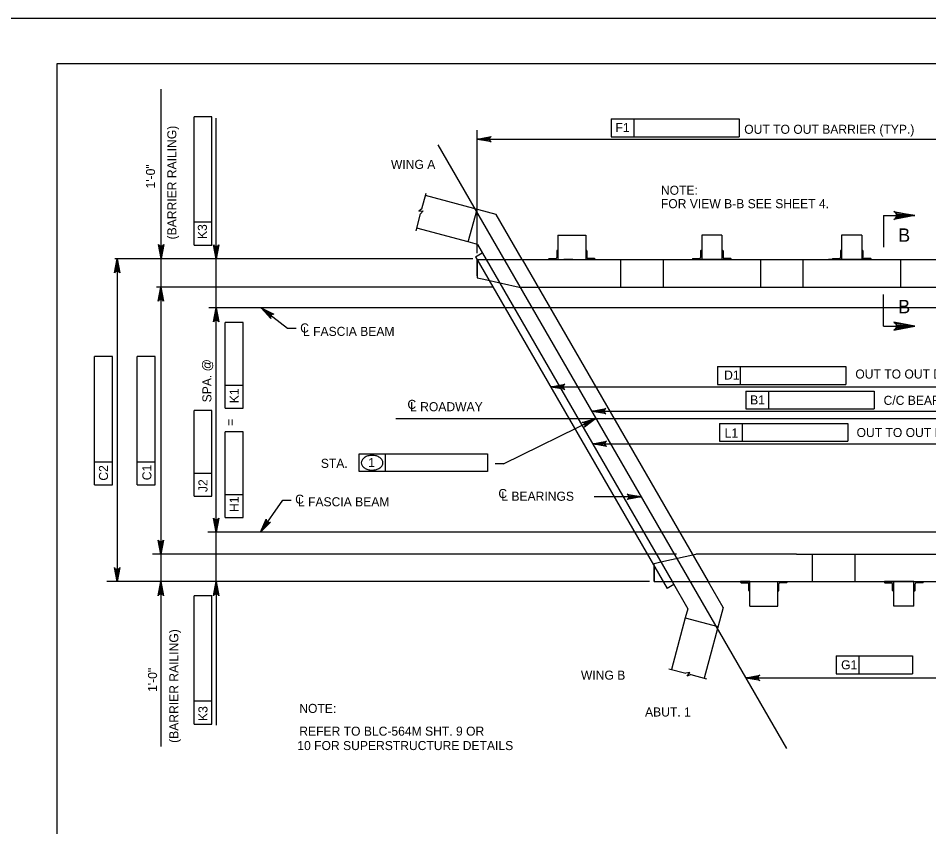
# Model space of a CAD drawing. Extents: x 638175 to 640495, y 294277 to 298435.
# Drawn here: x 639303.6 to 639605.4, y 298167.4 to 298435.5 of the extents above; entities that cross this region are included whole.
import ezdxf

# ---------------------------------------------------------------- set-up
doc = ezdxf.new("R2010")
doc.units = 0
for name, color, linetype in [('2', 7, 'Continuous'), ('3', 7, 'Continuous'), ('4', 7, 'Continuous'), ('PLT-BNDY', 7, 'Continuous')]:
    doc.layers.add(name, color=color, linetype=linetype)

msp = doc.modelspace()

# ---------------------------------------------------------------- linework, layer by layer
at = {"layer": '2'}
for p, q in [((639316.46, 297856.46), (639316.46, 298420.46)), ((639316.46, 298420.46), (640102.46, 298420.46)), ((639462.01, 298370.37), (639438.58, 298376.65)), ((639452.77, 298361.28), (639455.66, 298372.08)), ((639470.64, 298355.43), (639462.01, 298370.37)), ((639590.33, 298370.09), (639590.33, 298359.6)), ((639590.33, 298370.09), (639600.81, 298370.09)), ((639452.77, 298361.28), (639435.69, 298365.86)), ((639482.46, 298363.52), (639491.7, 298363.52)), ((639482.46, 298363.52), (639482.46, 298355.43)), ((639491.7, 298363.52), (639491.7, 298355.43)), ((639536.85, 298363.52), (639530.13, 298363.52)), ((639530.13, 298363.52), (639530.13, 298355.43)), ((639536.85, 298363.52), (639536.85, 298355.43)), ((639583.22, 298363.52), (639576.49, 298363.52)), ((639576.49, 298363.52), (639576.49, 298355.43)), ((639583.22, 298363.52), (639583.22, 298355.43)), ((639455.79, 298360.47), (639452.77, 298361.28)), ((639455.79, 298360.47), (639458.7, 298355.43)), ((639455.17, 298356.38), (639457.41, 298357.67)), ((639482.1, 298358.34), (639482.1, 298356.15)), ((639482.28, 298358.52), (639482.46, 298358.52)), ((639482.46, 298358.52), (639482.46, 298355.43)), ((639491.88, 298358.52), (639491.7, 298358.52)), ((639491.7, 298358.52), (639491.7, 298355.43)), ((639492.06, 298358.34), (639492.06, 298356.15)), ((639529.76, 298358.34), (639529.76, 298356.15)), ((639529.95, 298358.52), (639530.13, 298358.52)), ((639530.13, 298358.52), (639530.13, 298355.43)), ((639537.04, 298358.52), (639536.85, 298358.52)), ((639536.85, 298358.52), (639536.85, 298355.43)), ((639537.22, 298358.34), (639537.22, 298356.15)), ((639576.13, 298358.34), (639576.13, 298356.15)), ((639576.31, 298358.52), (639576.49, 298358.52)), ((639576.49, 298358.52), (639576.49, 298355.43)), ((639583.4, 298358.52), (639583.22, 298358.52)), ((639583.22, 298358.52), (639583.22, 298355.43)), ((639583.58, 298358.34), (639583.58, 298356.15)), ((639455.17, 298356.38), (639518.64, 298246.45)), ((639455.72, 298355.43), (639660.35, 298355.43)), ((639455.72, 298355.43), (639455.72, 298349.4)), ((639455.72, 298350.04), (639455.72, 298355.43)), ((639458.7, 298355.43), (639520.32, 298248.7)), ((639470.64, 298355.43), (639532.26, 298248.7)), ((639479.37, 298355.61), (639479.37, 298355.43)), ((639479.55, 298355.79), (639481.74, 298355.79)), ((639482.46, 298355.43), (639491.7, 298355.43)), ((639487.46, 298355.43), (639484.37, 298355.43)), ((639491.7, 298355.43), (639494.79, 298355.43)), ((639494.61, 298355.79), (639492.43, 298355.79)), ((639494.79, 298355.61), (639494.79, 298355.43)), ((639503.25, 298355.43), (639503.25, 298346.31)), ((639517.32, 298355.43), (639517.32, 298346.31)), ((639527.04, 298355.61), (639527.04, 298355.43)), ((639530.13, 298355.43), (639527.04, 298355.43)), ((639527.22, 298355.79), (639529.4, 298355.79)), ((639538.11, 298355.43), (639528.87, 298355.43)), ((639536.85, 298355.43), (639530.13, 298355.43)), ((639536.85, 298355.43), (639539.95, 298355.43)), ((639539.76, 298355.79), (639537.58, 298355.79)), ((639539.95, 298355.61), (639539.95, 298355.43)), ((639549.66, 298355.43), (639549.66, 298346.31)), ((639563.68, 298355.43), (639563.69, 298346.31)), ((639575.24, 298355.43), (639572.15, 298355.43)), ((639573.4, 298355.61), (639573.4, 298355.43)), ((639576.49, 298355.43), (639573.4, 298355.43)), ((639573.58, 298355.79), (639575.76, 298355.79)), ((639584.47, 298355.43), (639575.24, 298355.43)), ((639583.22, 298355.43), (639576.49, 298355.43)), ((639583.22, 298355.43), (639586.31, 298355.43)), ((639586.13, 298355.79), (639583.95, 298355.79)), ((639584.47, 298355.43), (639587.56, 298355.43)), ((639586.31, 298355.61), (639586.31, 298355.43)), ((639596.02, 298355.43), (639596.02, 298346.31)), ((639455.72, 298349.4), (639457.89, 298348.91)), ((639457.89, 298348.91), (639469.57, 298346.31)), ((639469.57, 298346.31), (639646.49, 298346.31)), ((639590.33, 298333.36), (639590.33, 298343.84)), ((639590.33, 298333.36), (639600.81, 298333.36)), ((639516.53, 298255.22), (639528.2, 298257.82)), ((639561.51, 298257.82), (639528.2, 298257.82)), ((639561.51, 298257.82), (639707.31, 298257.82)), ((639566.89, 298248.7), (639566.89, 298257.82)), ((639580.96, 298248.7), (639580.96, 298257.82)), ((639514.35, 298254.73), (639516.53, 298255.22)), ((639514.35, 298248.7), (639514.35, 298254.73)), ((639514.35, 298253.87), (639514.35, 298248.7)), ((639514.35, 298248.7), (639718.99, 298248.7)), ((639520.32, 298248.7), (639525.5, 298239.72)), ((639537.19, 298240.16), (639532.26, 298248.7)), ((639543.01, 298248.52), (639543.01, 298248.7)), ((639546.1, 298248.7), (639543.01, 298248.7)), ((639543.19, 298248.34), (639545.37, 298248.34)), ((639546.1, 298248.7), (639555.34, 298248.7)), ((639546.1, 298245.61), (639546.1, 298248.7)), ((639546.1, 298240.61), (639546.1, 298248.7)), ((639555.34, 298248.7), (639558.43, 298248.7)), ((639555.34, 298245.61), (639555.34, 298248.7)), ((639555.34, 298240.61), (639555.34, 298248.7)), ((639558.25, 298248.34), (639556.06, 298248.34)), ((639558.43, 298248.52), (639558.43, 298248.7)), ((639590.67, 298248.52), (639590.67, 298248.7)), ((639593.76, 298248.7), (639590.67, 298248.7)), ((639590.85, 298248.34), (639593.04, 298248.34)), ((639600.49, 298248.7), (639593.76, 298248.7)), ((639593.76, 298245.61), (639593.76, 298248.7)), ((639593.76, 298240.61), (639593.76, 298248.7)), ((639600.49, 298245.61), (639600.49, 298248.7)), ((639600.49, 298248.7), (639603.58, 298248.7)), ((639600.49, 298240.61), (639600.49, 298248.7)), ((639603.4, 298248.34), (639601.22, 298248.34)), ((639603.58, 298248.52), (639603.58, 298248.7)), ((639520.87, 298247.75), (639518.64, 298246.45)), ((639545.74, 298245.79), (639545.74, 298247.97)), ((639545.92, 298245.61), (639546.1, 298245.61)), ((639555.52, 298245.61), (639555.34, 298245.61)), ((639555.7, 298245.79), (639555.7, 298247.97)), ((639593.4, 298245.79), (639593.4, 298247.97)), ((639593.58, 298245.61), (639593.76, 298245.61)), ((639600.67, 298245.61), (639600.49, 298245.61)), ((639600.85, 298245.79), (639600.85, 298247.97)), ((639525.5, 298239.72), (639524.69, 298236.7)), ((639537.19, 298240.16), (639530.91, 298216.73)), ((639546.1, 298240.61), (639555.34, 298240.61)), ((639600.49, 298240.61), (639593.76, 298240.61)), ((639524.69, 298236.7), (639520.12, 298219.62)), ((639524.69, 298236.7), (639535.49, 298233.81))]:
    msp.add_line(p, q, dxfattribs=at)
for points in [[(639600.81, 298370.09), (639593.82, 298368.78), (639594.36, 298369.15), (639594.64, 298369.62), (639594.72, 298370.09), (639594.64, 298370.56), (639594.36, 298371.03), (639593.82, 298371.4), (639600.81, 298370.09), (639594.36, 298371.03), (639594.64, 298370.56), (639600.81, 298370.09), (639594.72, 298370.09), (639594.64, 298369.62), (639600.81, 298370.09), (639594.36, 298369.15)], [(639600.81, 298333.36), (639593.82, 298334.67), (639594.36, 298334.3), (639594.64, 298333.83), (639594.72, 298333.36), (639594.64, 298332.89), (639594.36, 298332.42), (639593.82, 298332.05), (639600.81, 298333.36), (639594.36, 298332.42), (639594.64, 298332.89), (639600.81, 298333.36), (639594.72, 298333.36), (639594.64, 298333.83), (639600.81, 298333.36), (639594.36, 298334.3)]]:
    msp.add_lwpolyline(points, dxfattribs=at)
for centre, radius, start, end in [((639482.28, 298358.34), 0.182, 90, 179.9984), ((639491.88, 298358.34), 0.182, 0.0016, 90), ((639529.95, 298358.34), 0.182, 90, 179.9984), ((639537.04, 298358.34), 0.182, 0.0016, 90), ((639576.31, 298358.34), 0.182, 90, 179.9984), ((639583.4, 298358.34), 0.182, 0.0016, 90), ((639479.55, 298355.61), 0.182, 90, 179.9984), ((639481.74, 298356.15), 0.364, 270, 359.9984), ((639492.43, 298356.15), 0.364, 180.0016, 270), ((639494.61, 298355.61), 0.182, 0.0016, 90), ((639527.22, 298355.61), 0.182, 90, 179.9984), ((639529.4, 298356.15), 0.364, 270, 359.9984), ((639537.58, 298356.15), 0.364, 180.0016, 270), ((639539.76, 298355.61), 0.182, 0.0016, 90), ((639573.58, 298355.61), 0.182, 90, 179.9984), ((639575.76, 298356.15), 0.364, 270, 359.9984), ((639583.95, 298356.15), 0.364, 180.0016, 270), ((639586.13, 298355.61), 0.182, 0.0016, 90), ((639543.19, 298248.52), 0.182, 180.0016, 270), ((639545.37, 298247.97), 0.364, 0.0016, 90), ((639556.06, 298247.97), 0.364, 90, 179.9984), ((639558.25, 298248.52), 0.182, 270, 359.9984), ((639590.85, 298248.52), 0.182, 180.0016, 270), ((639593.04, 298247.97), 0.364, 0.0016, 90), ((639601.22, 298247.97), 0.364, 90, 179.9984), ((639603.4, 298248.52), 0.182, 270, 359.9984), ((639545.92, 298245.79), 0.182, 180.0016, 270), ((639555.52, 298245.79), 0.182, 270, 359.9984), ((639593.58, 298245.79), 0.182, 180.0016, 270), ((639600.67, 298245.79), 0.182, 270, 359.9984)]:
    msp.add_arc(centre, radius, start, end, dxfattribs=at)
at = {"layer": '3'}
for p, q in [((639442.68, 298393.51), (639558.23, 298193.38)), ((639437.41, 298372.29), (639438.78, 298377.42)), ((639437.41, 298372.29), (639436.36, 298371.51)), ((639435.46, 298365.02), (639436.96, 298370.62)), ((639436.36, 298371.51), (639437.85, 298371.6)), ((639437.85, 298371.6), (639436.96, 298370.62)), ((639519.28, 298219.85), (639524.88, 298218.34)), ((639526.17, 298218.63), (639524.88, 298218.34)), ((639525.35, 298217.38), (639526.17, 298218.63)), ((639526.55, 298217.9), (639525.35, 298217.38)), ((639526.55, 298217.9), (639531.68, 298216.52))]:
    msp.add_line(p, q, dxfattribs=at)
at = {"layer": '4'}
for p, q in [((639350.84, 298411.99), (639350.84, 298194.06)), ((639367.76, 298402.79), (639361.85, 298402.8)), ((639361.85, 298367.84), (639361.85, 298402.8)), ((639367.76, 298360.27), (639367.76, 298402.79)), ((639369.17, 298361.36), (639369.17, 298402.36)), ((639500.06, 298402.09), (639507.62, 298402.09)), ((639500.06, 298402.09), (639500.06, 298396.19)), ((639507.62, 298402.09), (639507.62, 298396.19)), ((639507.62, 298402.09), (639542.58, 298402.09)), ((639542.58, 298402.09), (639542.58, 298396.19)), ((639455.72, 298357.54), (639455.72, 298398.36)), ((639500.06, 298396.19), (639542.58, 298396.19)), ((639455.72, 298395.34), (639660.35, 298395.34)), ((639361.85, 298360.28), (639361.85, 298367.84)), ((639367.76, 298367.83), (639361.85, 298367.84)), ((639361.85, 298360.28), (639367.76, 298360.27)), ((639369.17, 298358.53), (639369.17, 298361.36)), ((639454.28, 298355.69), (639335.65, 298355.69)), ((639336.38, 298355.69), (639336.38, 298249.4)), ((639369.17, 298248.7), (639369.17, 298355.69)), ((639461.08, 298346.31), (639349.36, 298346.31)), ((639667.19, 298339.46), (639366.77, 298339.46)), ((639384.12, 298339.46), (639392.81, 298332.77)), ((639378.12, 298334.57), (639372.21, 298334.57)), ((639372.21, 298313.73), (639372.21, 298334.57)), ((639378.12, 298306.16), (639378.12, 298334.57)), ((639392.81, 298332.77), (639395.65, 298332.77)), ((639334.79, 298323.28), (639328.88, 298323.28)), ((639328.88, 298288.32), (639328.88, 298323.28)), ((639334.79, 298280.76), (639334.79, 298323.28)), ((639348.95, 298323.28), (639343.05, 298323.28)), ((639343.05, 298288.32), (639343.05, 298323.28)), ((639348.95, 298280.76), (639348.95, 298323.28)), ((639535.36, 298320.01), (639542.92, 298320.01)), ((639535.36, 298320.01), (639535.36, 298314.1)), ((639542.92, 298320.01), (639542.92, 298314.1)), ((639542.92, 298320.01), (639577.88, 298320.01)), ((639577.88, 298320.01), (639577.88, 298314.1)), ((639378.12, 298313.72), (639372.21, 298313.73)), ((639372.21, 298306.17), (639372.21, 298313.73)), ((639480.07, 298313.25), (639681.72, 298313.25)), ((639535.36, 298314.1), (639577.88, 298314.1)), ((639544.74, 298311.88), (639587.26, 298311.88)), ((639544.74, 298311.88), (639544.74, 298305.98)), ((639552.3, 298311.88), (639552.3, 298305.98)), ((639587.26, 298311.88), (639587.26, 298305.98)), ((639372.21, 298306.17), (639378.12, 298306.16)), ((639544.74, 298305.98), (639587.26, 298305.98)), ((639367.76, 298305.4), (639361.85, 298305.4)), ((639361.85, 298284.56), (639361.85, 298305.4)), ((639367.76, 298276.99), (639367.76, 298305.4)), ((639428.79, 298302.82), (639730.34, 298302.82)), ((639464.45, 298287.73), (639495.03, 298302.77)), ((639493.67, 298305.2), (639677.42, 298305.2)), ((639535.99, 298301.17), (639543.55, 298301.17)), ((639535.99, 298301.17), (639535.99, 298295.27)), ((639543.55, 298301.17), (639543.55, 298295.27)), ((639543.55, 298301.17), (639578.51, 298301.17)), ((639578.51, 298301.17), (639578.51, 298295.27)), ((639378.12, 298298.34), (639372.21, 298298.35)), ((639372.21, 298277.5), (639372.21, 298298.35)), ((639378.12, 298269.93), (639378.12, 298298.34)), ((639493.93, 298294.42), (639689.61, 298294.42)), ((639535.99, 298295.27), (639578.51, 298295.27)), ((639416.64, 298285.18), (639416.64, 298291.08)), ((639416.64, 298291.08), (639424.21, 298291.08)), ((639424.21, 298291.08), (639459.16, 298291.08)), ((639425.29, 298285.18), (639425.29, 298291.08)), ((639459.16, 298291.08), (639459.16, 298285.18)), ((639328.88, 298280.76), (639328.88, 298288.32)), ((639334.79, 298288.32), (639328.88, 298288.32)), ((639343.05, 298280.76), (639343.05, 298288.32)), ((639348.95, 298288.32), (639343.05, 298288.32)), ((639464.45, 298287.73), (639461.62, 298287.73)), ((639361.85, 298277), (639361.85, 298284.56)), ((639367.76, 298284.55), (639361.85, 298284.56)), ((639459.16, 298285.18), (639416.64, 298285.18)), ((639328.88, 298280.76), (639334.79, 298280.76)), ((639343.05, 298280.76), (639348.95, 298280.76)), ((639361.85, 298277), (639367.76, 298276.99)), ((639372.21, 298269.94), (639372.21, 298277.5)), ((639378.12, 298277.5), (639372.21, 298277.5)), ((639383.83, 298265.1), (639391.26, 298275.72)), ((639391.26, 298275.72), (639394.09, 298275.72)), ((639510.04, 298276.85), (639494.53, 298276.85)), ((639372.21, 298269.94), (639378.12, 298269.93)), ((639708.19, 298265.1), (639366.47, 298265.1)), ((639521.82, 298257.82), (639348.11, 298257.82)), ((639512.79, 298248.7), (639333, 298248.7)), ((639369.17, 298245.87), (639369.17, 298243.03)), ((639367.76, 298244.01), (639361.85, 298244.02)), ((639361.85, 298209.06), (639361.85, 298244.02)), ((639367.76, 298201.49), (639367.76, 298244.01)), ((639369.17, 298243.03), (639369.17, 298201.08)), ((639574.66, 298224.08), (639582.22, 298224.08)), ((639574.66, 298224.08), (639574.66, 298218.18)), ((639582.22, 298224.08), (639582.22, 298218.18)), ((639582.22, 298224.08), (639599.98, 298224.08)), ((639599.98, 298224.08), (639599.98, 298218.18)), ((639574.66, 298218.18), (639599.98, 298218.18)), ((639544.7, 298216.82), (639728.45, 298216.82)), ((639361.85, 298201.5), (639361.85, 298209.06)), ((639367.76, 298209.05), (639361.85, 298209.06)), ((639361.85, 298201.5), (639367.76, 298201.49))]:
    msp.add_line(p, q, dxfattribs=at)
for points in [[(639455.72, 298395.34), (639460.38, 298396.21), (639460.02, 298395.96), (639459.84, 298395.65), (639459.78, 298395.34), (639459.84, 298395.02), (639460.02, 298394.71), (639460.38, 298394.46), (639455.72, 298395.34), (639460.02, 298394.71), (639459.84, 298395.02), (639455.72, 298395.34), (639459.78, 298395.34), (639459.84, 298395.65), (639455.72, 298395.34), (639460.02, 298395.96)], [(639350.99, 298355.77), (639350.12, 298360.43), (639350.37, 298360.07), (639350.68, 298359.88), (639350.99, 298359.83), (639351.31, 298359.88), (639351.62, 298360.07), (639351.87, 298360.43), (639350.99, 298355.77), (639351.62, 298360.07), (639351.31, 298359.88), (639350.99, 298355.77), (639350.99, 298359.83), (639350.68, 298359.88), (639350.99, 298355.77), (639350.37, 298360.07)], [(639369.17, 298355.69), (639368.3, 298360.35), (639368.55, 298360), (639368.86, 298359.81), (639369.17, 298359.76), (639369.48, 298359.81), (639369.8, 298360), (639370.04, 298360.35), (639369.17, 298355.69), (639369.8, 298360), (639369.48, 298359.81), (639369.17, 298355.69), (639369.17, 298359.76), (639368.86, 298359.81), (639369.17, 298355.69), (639368.55, 298360)], [(639336.38, 298355.69), (639337.26, 298351.03), (639337.01, 298351.39), (639336.7, 298351.58), (639336.38, 298351.63), (639336.07, 298351.58), (639335.76, 298351.39), (639335.51, 298351.03), (639336.38, 298355.69), (639335.76, 298351.39), (639336.07, 298351.58), (639336.38, 298355.69), (639336.38, 298351.63), (639336.7, 298351.58), (639336.38, 298355.69), (639337.01, 298351.39)], [(639350.84, 298346.31), (639351.71, 298341.65), (639351.46, 298342), (639351.15, 298342.19), (639350.84, 298342.24), (639350.53, 298342.19), (639350.21, 298342), (639349.97, 298341.65), (639350.84, 298346.31), (639350.21, 298342), (639350.53, 298342.19), (639350.84, 298346.31), (639350.84, 298342.24), (639351.15, 298342.19), (639350.84, 298346.31), (639351.46, 298342)], [(639369.17, 298339.46), (639370.04, 298334.8), (639369.8, 298335.15), (639369.48, 298335.34), (639369.17, 298335.39), (639368.86, 298335.34), (639368.55, 298335.15), (639368.3, 298334.8), (639369.17, 298339.46), (639368.55, 298335.15), (639368.86, 298335.34), (639369.17, 298339.46), (639369.17, 298335.39), (639369.48, 298335.34), (639369.17, 298339.46), (639369.8, 298335.15)], [(639384.12, 298339.46), (639388.35, 298337.31), (639387.91, 298337.33), (639387.57, 298337.19), (639387.34, 298336.98), (639387.19, 298336.7), (639387.15, 298336.34), (639387.28, 298335.92), (639384.12, 298339.46), (639387.15, 298336.34), (639387.19, 298336.7), (639384.12, 298339.46), (639387.34, 298336.98), (639387.57, 298337.19), (639384.12, 298339.46), (639387.91, 298337.33)], [(639480.07, 298313.25), (639484.73, 298314.13), (639484.37, 298313.88), (639484.19, 298313.57), (639484.13, 298313.25), (639484.19, 298312.94), (639484.37, 298312.63), (639484.73, 298312.38), (639480.07, 298313.25), (639484.37, 298312.63), (639484.19, 298312.94), (639480.07, 298313.25), (639484.13, 298313.25), (639484.19, 298313.57), (639480.07, 298313.25), (639484.37, 298313.88)], [(639493.67, 298305.2), (639498.33, 298306.07), (639497.97, 298305.82), (639497.79, 298305.51), (639497.73, 298305.2), (639497.79, 298304.89), (639497.97, 298304.57), (639498.33, 298304.33), (639493.67, 298305.2), (639497.97, 298304.57), (639497.79, 298304.89), (639493.67, 298305.2), (639497.73, 298305.2), (639497.79, 298305.51), (639493.67, 298305.2), (639497.97, 298305.82)], [(639495.03, 298302.77), (639491.24, 298299.93), (639491.45, 298300.32), (639491.48, 298300.68), (639491.39, 298300.98), (639491.2, 298301.24), (639490.9, 298301.44), (639490.46, 298301.5), (639495.03, 298302.77), (639490.9, 298301.44), (639491.2, 298301.24), (639495.03, 298302.77), (639491.39, 298300.98), (639491.48, 298300.68), (639495.03, 298302.77), (639491.45, 298300.32)], [(639493.93, 298294.42), (639498.59, 298295.29), (639498.23, 298295.05), (639498.04, 298294.73), (639497.99, 298294.42), (639498.04, 298294.11), (639498.23, 298293.8), (639498.59, 298293.55), (639493.93, 298294.42), (639498.23, 298293.8), (639498.04, 298294.11), (639493.93, 298294.42), (639497.99, 298294.42), (639498.04, 298294.73), (639493.93, 298294.42), (639498.23, 298295.05)], [(639510.04, 298276.85), (639505.38, 298275.97), (639505.74, 298276.22), (639505.92, 298276.53), (639505.98, 298276.85), (639505.92, 298277.16), (639505.74, 298277.47), (639505.38, 298277.72), (639510.04, 298276.85), (639505.74, 298277.47), (639505.92, 298277.16), (639510.04, 298276.85), (639505.98, 298276.85), (639505.92, 298276.53), (639510.04, 298276.85), (639505.74, 298276.22)], [(639369.17, 298265.1), (639368.3, 298269.76), (639368.55, 298269.4), (639368.86, 298269.22), (639369.17, 298269.16), (639369.48, 298269.22), (639369.8, 298269.4), (639370.04, 298269.76), (639369.17, 298265.1), (639369.8, 298269.4), (639369.48, 298269.22), (639369.17, 298265.1), (639369.17, 298269.16), (639368.86, 298269.22), (639369.17, 298265.1), (639368.55, 298269.4)], [(639383.83, 298265.1), (639385.79, 298269.42), (639385.79, 298268.98), (639385.94, 298268.65), (639386.16, 298268.43), (639386.45, 298268.3), (639386.81, 298268.27), (639387.22, 298268.42), (639383.83, 298265.1), (639386.81, 298268.27), (639386.45, 298268.3), (639383.83, 298265.1), (639386.16, 298268.43), (639385.94, 298268.65), (639383.83, 298265.1), (639385.79, 298268.98)], [(639350.84, 298257.82), (639349.97, 298262.48), (639350.21, 298262.12), (639350.53, 298261.94), (639350.84, 298261.89), (639351.15, 298261.94), (639351.46, 298262.12), (639351.71, 298262.48), (639350.84, 298257.82), (639351.46, 298262.12), (639351.15, 298261.94), (639350.84, 298257.82), (639350.84, 298261.89), (639350.53, 298261.94), (639350.84, 298257.82), (639350.21, 298262.12)], [(639336.38, 298248.7), (639335.51, 298253.36), (639335.76, 298253), (639336.07, 298252.82), (639336.38, 298252.76), (639336.7, 298252.82), (639337.01, 298253), (639337.26, 298253.36), (639336.38, 298248.7), (639337.01, 298253), (639336.7, 298252.82), (639336.38, 298248.7), (639336.38, 298252.76), (639336.07, 298252.82), (639336.38, 298248.7), (639335.76, 298253)], [(639350.84, 298248.7), (639351.71, 298244.04), (639351.46, 298244.4), (639351.15, 298244.58), (639350.84, 298244.64), (639350.53, 298244.58), (639350.21, 298244.4), (639349.97, 298244.04), (639350.84, 298248.7), (639350.21, 298244.4), (639350.53, 298244.58), (639350.84, 298248.7), (639350.84, 298244.64), (639351.15, 298244.58), (639350.84, 298248.7), (639351.46, 298244.4)], [(639369.17, 298248.7), (639370.04, 298244.04), (639369.8, 298244.4), (639369.48, 298244.58), (639369.17, 298244.64), (639368.86, 298244.58), (639368.55, 298244.4), (639368.3, 298244.04), (639369.17, 298248.7), (639368.55, 298244.4), (639368.86, 298244.58), (639369.17, 298248.7), (639369.17, 298244.64), (639369.48, 298244.58), (639369.17, 298248.7), (639369.8, 298244.4)], [(639544.7, 298216.82), (639549.36, 298217.69), (639549, 298217.44), (639548.81, 298217.13), (639548.76, 298216.82), (639548.81, 298216.51), (639549, 298216.19), (639549.36, 298215.95), (639544.7, 298216.82), (639549, 298216.19), (639548.81, 298216.51), (639544.7, 298216.82), (639548.76, 298216.82), (639548.81, 298217.13), (639544.7, 298216.82), (639549, 298217.44)]]:
    msp.add_lwpolyline(points, dxfattribs=at)
for centre, radius, start, end in [((639420.88, 298285.28), 5.27, 90, 105.6708), ((639420.88, 298285.28), 5.27, 74.3292, 90), ((639418.97, 298288.12), 1.68, 148.5507, 180), ((639418.97, 298288.12), 1.68, 180, 211.4493), ((639419.88, 298287.56), 2.75, 124.109, 148.5507), ((639420.48, 298286.68), 3.82, 105.6708, 124.109), ((639421.27, 298286.68), 3.82, 55.891, 74.3292), ((639421.87, 298287.56), 2.75, 31.4493, 55.891), ((639422.78, 298288.12), 1.68, 0, 31.4493), ((639422.78, 298288.12), 1.68, 328.5507, 0), ((639419.88, 298288.68), 2.75, 211.4493, 235.891), ((639420.48, 298289.56), 3.82, 235.891, 254.3292), ((639420.88, 298290.96), 5.27, 254.3292, 270), ((639420.88, 298290.96), 5.27, 270, 285.6708), ((639421.27, 298289.56), 3.82, 285.6708, 304.109), ((639421.87, 298288.68), 2.75, 304.109, 328.5507)]:
    msp.add_arc(centre, radius, start, end, dxfattribs=at)
at = {"layer": 'PLT-BNDY'}
msp.add_lwpolyline([(639276.46, 298435.46), (640117.46, 298435.46), (640117.46, 297841.46), (639276.46, 297841.46)], close=True, dxfattribs=at)

# ---------------------------------------------------------------- texts
at = {"layer": '4'}
for s, height, rotation, p in [('(BARRIER RAILING)', 3, 90, (639356, 298362.14)), ('F1', 3, 359.9382, (639501.54, 298397.71)), ('1\'-0"', 3, 90, (639348.93, 298379.03)), ('K3', 3, 89.9382, (639366.11, 298362.26)), ('B', 4.43, 360, (639595.27, 298361.36)), ('SPA. @', 3, 90, (639367.61, 298308.14)), ('D1', 3, 359.9382, (639537.55, 298315.68)), ('K1', 3, 89.9382, (639376.67, 298307.85)), ('B1', 3, 359.9382, (639546.18, 298307.43)), ('=', 3, 90, (639375.34, 298300.37)), ('L1', 3, 359.9382, (639537.73, 298296.47)), ('C2', 3, 89.9382, (639333.33, 298282.17)), ('C1', 3, 89.9382, (639347.72, 298282.31)), ('J2', 3, 89.9382, (639366.31, 298278.39)), ('H1', 3, 89.9382, (639376.67, 298271.79)), ('(BARRIER RAILING)', 3, 90, (639356.66, 298195.26)), ('G1', 3, 359.9382, (639576.33, 298219.63)), ('1\'-0"', 3, 90, (639349.59, 298212.15)), ('K3', 3, 89.9382, (639366.31, 298202.52))]:
    msp.add_text(s, height=height, rotation=rotation, dxfattribs=at).set_placement(p)
for s, height, p in [('OUT TO OUT BARRIER (TYP.)', 3, (639544.22, 298397.14)), ('WING A', 3, (639427.12, 298385.5)), ('NOTE:', 3, (639516.6, 298376.93)), ('FOR VIEW B-B SEE SHEET 4.', 3, (639516.6, 298372.49)), ('B', 4.43, (639595.27, 298337.65)), ('C', 3, (639397.04, 298331.28)), ('L FASCIA BEAM', 3, (639397.98, 298330.15)), ('OUT TO OUT DECKING', 3, (639581.05, 298316.02)), ('C', 3, (639432.58, 298305.95)), ('C/C BEARINGS', 3, (639590.41, 298307.29)), ('L ROADWAY', 3, (639433.46, 298305.19)), ('OUT TO OUT BEAM', 3, (639581.46, 298296.63)), ('STA.', 3, (639403.88, 298286.41)), ('1', 3, (639419.57, 298286.66)), ('C', 3, (639462.73, 298276.41)), ('L BEARINGS', 3, (639463.71, 298275.51)), ('C', 3, (639395.38, 298274.53)), ('L FASCIA BEAM', 3, (639396.3, 298273.67)), ('WING B', 3, (639490.09, 298216.21)), ('NOTE:', 3, (639396.74, 298205.18)), ('ABUT. 1', 3, (639511.34, 298204)), ('REFER TO BLC-564M SHT. 9 OR', 3, (639396.74, 298197.64)), ('10 FOR SUPERSTRUCTURE DETAILS', 3, (639396.09, 298192.87))]:
    msp.add_text(s, height=height, dxfattribs=at).set_placement(p)

doc.saveas('drawing.dxf')
